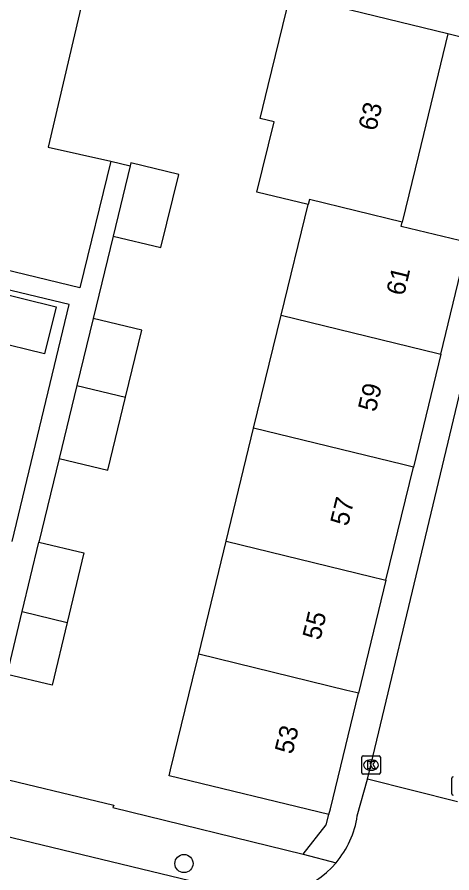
# Model space of a CAD drawing. Extents: x 162812 to 163818, y 381639 to 382470.
# Drawn here: x 163295.16 to 163318.59, y 382334.65 to 382380.76 of the extents above; entities that cross this region are included whole.
import ezdxf

# ---------------------------------------------------------------- set-up
doc = ezdxf.new("R2010")
doc.units = 0
for name, color, linetype in [('IMGEO_Boom', 7, 'Continuous'), ('IMGEO_Kolk', 7, 'Continuous'), ('IMGEO_Loofbos', 7, 'Continuous'), ('IMGEO_Pand', 7, 'Continuous'), ('IMGEO_Pand_nummerreeks', 7, 'Continuous'), ('IMGEO_Rijbaan_lokaal_open', 7, 'Continuous'), ('IMGEO_Voetpad_open', 7, 'Continuous')]:
    doc.layers.add(name, color=color, linetype=linetype)

msp = doc.modelspace()

# ---------------------------------------------------------------- linework, layer by layer
at = {"layer": 'IMGEO_Boom'}
msp.add_circle((163304.152, 382335.157), 0.489, dxfattribs=at)
at = {"layer": 'IMGEO_Kolk'}
for p, q in [((163313.811, 382340.964), (163314.663, 382340.964)), ((163313.736, 382340.038), (163313.736, 382340.89)), ((163314.224, 382340.744), (163314.249, 382340.744)), ((163314.737, 382340.89), (163314.737, 382340.038)), ((163314.247, 382340.184), (163314.222, 382340.184)), ((163314.663, 382339.964), (163313.811, 382339.964)), ((163318.589, 382338.909), (163318.589, 382339.761))]:
    msp.add_line(p, q, dxfattribs=at)
for points in [[(163313.811, 382340.964), (163314.663, 382340.964)], [(163313.736, 382340.038), (163313.736, 382340.89)], [(163314.057, 382340.664), (163314.18, 382340.664), (163314.18, 382340.513), (163314.31, 382340.664), (163314.474, 382340.664), (163314.328, 382340.513), (163314.481, 382340.264), (163314.329, 382340.264), (163314.244, 382340.428), (163314.18, 382340.361), (163314.18, 382340.264), (163314.057, 382340.264), (163314.057, 382340.664)], [(163314.737, 382340.89), (163314.737, 382340.038)], [(163314.663, 382339.964), (163313.811, 382339.964)], [(163318.589, 382338.909), (163318.589, 382339.761)]]:
    msp.add_lwpolyline(points, dxfattribs=at)
for centre, start, end in [((163313.813, 382340.888), 91.552, 178.448), ((163313.813, 382340.888), 91.552, 178.448), ((163314.661, 382340.888), 1.552, 88.448), ((163314.661, 382340.888), 1.552, 88.448), ((163313.813, 382340.04), 181.552, 268.448), ((163313.813, 382340.04), 181.552, 268.448), ((163314.661, 382340.04), 271.552, 358.448), ((163314.661, 382340.04), 271.552, 358.448), ((163318.666, 382339.759), 91.552, 178.448), ((163318.666, 382339.759), 91.552, 178.448), ((163318.666, 382338.911), 181.552, 268.448), ((163318.666, 382338.911), 181.552, 268.448)]:
    msp.add_arc(centre, 0.0765, start, end, dxfattribs=at)
for centre, major_axis, ratio, start_param, end_param in [((163314.223, 382340.464), (-0.387, 0.002), 0.722429, 4.712389, 7.853982), ((163314.248, 382340.464), (-0.39, 0.002), 0.717154, 1.570796, 4.712389)]:
    msp.add_ellipse(centre, major_axis=major_axis, ratio=ratio, start_param=start_param, end_param=end_param, dxfattribs=at)
at = {"layer": 'IMGEO_Loofbos'}
msp.add_lwpolyline([(163299.333, 382384.417), (163296.837, 382373.761), (163300.215, 382373.005)], dxfattribs=at)
at = {"layer": 'IMGEO_Pand'}
for points in [[(163310.838, 382370.659), (163308.087, 382371.328), (163309.01, 382375.125), (163308.255, 382375.308), (163308.687, 382377.082), (163309.867, 382381.939)], [(163318.38, 382379.87), (163309.867, 382381.939)], [(163318.38, 382379.87), (163316.79, 382373.33), (163315.911, 382369.715)], [(163300.335, 382368.968), (163302.916, 382368.34), (163303.874, 382372.279), (163301.293, 382372.907), (163301.253, 382372.741)], [(163301.253, 382372.741), (163300.335, 382368.968)], [(163309.388, 382364.696), (163310.838, 382370.659)], [(163315.911, 382369.715), (163310.923, 382370.927), (163310.838, 382370.659)], [(163317.998, 382362.603), (163319.449, 382368.613), (163317.651, 382369.044), (163315.854, 382369.476), (163315.911, 382369.715)], [(163291.662, 382366.537), (163297.267, 382365.158), (163296.642, 382362.617), (163291.05, 382363.992)], [(163299.263, 382364.525), (163298.387, 382360.922)], [(163301.007, 382360.285), (163301.883, 382363.888), (163299.263, 382364.525)], [(163307.908, 382358.608), (163309.388, 382364.696)], [(163309.388, 382364.696), (163317.851, 382362.639), (163317.998, 382362.603)], [(163317.998, 382362.603), (163316.518, 382356.515)], [(163298.387, 382360.922), (163297.431, 382356.988)], [(163298.387, 382360.922), (163301.007, 382360.285)], [(163297.431, 382356.988), (163300.05, 382356.351), (163301.007, 382360.285)], [(163306.427, 382352.519), (163307.908, 382358.608)], [(163316.518, 382356.515), (163316.371, 382356.551), (163315.952, 382356.653), (163307.908, 382358.608)], [(163315.038, 382350.426), (163316.518, 382356.515)], [(163304.947, 382346.43), (163306.427, 382352.519)], [(163306.427, 382352.519), (163314.286, 382350.609), (163314.891, 382350.462), (163315.038, 382350.426)], [(163295.436, 382348.742), (163296.335, 382352.48)], [(163296.335, 382352.48), (163298.766, 382351.896), (163297.865, 382348.151)], [(163315.038, 382350.426), (163313.557, 382344.337)], [(163294.619, 382345.345), (163295.436, 382348.742)], [(163295.436, 382348.742), (163297.865, 382348.151)], [(163297.865, 382348.151), (163297.05, 382344.76), (163294.619, 382345.345)], [(163311.967, 382337.792), (163303.356, 382339.886), (163303.432, 382340.197), (163304.613, 382345.056), (163304.947, 382346.43)], [(163313.557, 382344.337), (163313.41, 382344.373), (163312.935, 382344.488), (163304.947, 382346.43)], [(163311.967, 382337.792), (163312.042, 382338.103), (163313.557, 382344.337)]]:
    msp.add_lwpolyline(points, dxfattribs=at)
at = {"layer": 'IMGEO_Rijbaan_lokaal_open'}
for points in [[(163314.048, 382339.705), (163320.911, 382368.368)], [(163306.632, 382333.703), (163233.817, 382351.293)], [(163313.492, 382337.723), (163314.048, 382339.705)], [(163318.898, 382338.486), (163314.048, 382339.705)]]:
    msp.add_lwpolyline(points, dxfattribs=at)
for centre, radius, start, end in [((163308.486, 382338.471), 5.062, 319.7313, 351.5039), ((163308.479, 382338.469), 5.066, 253.4458, 319.7963)]:
    msp.add_arc(centre, radius, start, end, dxfattribs=at)
at = {"layer": 'IMGEO_Voetpad_open'}
for points in [[(163300.215, 382373.005), (163298.551, 382366.172), (163254.812, 382376.767), (163256.514, 382383.879)], [(163344.924, 382373.332), (163318.38, 382379.87)], [(163294.891, 382352.5), (163297.971, 382365.286), (163255.017, 382375.57), (163251.946, 382362.826)], [(163300.215, 382373.005), (163301.253, 382372.741)], [(163300.335, 382368.968), (163299.263, 382364.525)], [(163297.431, 382356.988), (163296.335, 382352.48)], [(163293.334, 382339.995), (163300.366, 382338.298), (163300.326, 382338.172), (163310.581, 382335.665)], [(163310.581, 382335.665), (163311.822, 382337.237), (163311.967, 382337.792)], [(163310.581, 382335.665), (163312.348, 382335.199)]]:
    msp.add_lwpolyline(points, dxfattribs=at)

# ---------------------------------------------------------------- texts
at = {"layer": 'IMGEO_Pand_nummerreeks'}
for s, rotation, p in [('63', 76.3347, (163314.502, 382374.585)), ('61', 76.3352, (163316.003, 382365.703)), ('59', 76.3352, (163314.481, 382359.446)), ('57', 76.3352, (163312.987, 382353.299)), ('55', 76.3352, (163311.493, 382347.152)), ('53', 76.3352, (163309.998, 382341.005))]:
    msp.add_text(s, height=1, rotation=rotation, dxfattribs=at).set_placement(p)

doc.saveas('drawing.dxf')
